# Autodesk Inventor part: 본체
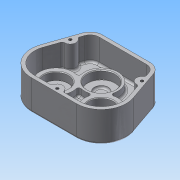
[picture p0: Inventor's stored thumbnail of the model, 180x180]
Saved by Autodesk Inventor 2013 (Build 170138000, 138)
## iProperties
Created: 2014-12
Part Number: 본체
Material: 알루미늄 6061
Document SubType Name: Modeling
Designer: Administrator
Mass: 614.49 g
Surface Area: 669.655 cm^2
Volume: 226.749 cm^3
Density: 2.71 g/cm^3
Author: Administrator
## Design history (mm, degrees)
sketch "스케치1"
  geometry: L1 (0, 32.527)-(-32.527, 0); L2 (0, 32.527)-(32.527, 0); L3 (47, 68.527)-(-47, 68.527); L4 (-66.565, 11.723)-(-47, 68.527); L5 (66.565, 11.723)-(47, 68.527); L6 (-32.527, -36)-(32.527, -36); A1 r 36 centre (-32.527, 0) between (-66.565, 11.723) and (-32.527, -36); A2 r 36 centre (32.527, 0) between (32.527, -36) and (66.565, 11.723); 1 further point
  constraints: 12 end point, 4 point on circle, 4 tangent, 2 centre point, 2 horizontal alignment, 1 equal length, 1 horizontal, 1 vertical alignment
  dimensions: "d0" = 72 diameter of A1; "d1" = 72 diameter of A2; "d3" = 90 deg angle of L1 L2; "d4" = 36 distance from line of L3 L1.start; "d5" = 94 distance of L3.start L3.end; "d25" = 46 distance of L1.start L1.end; "d26" = 46 distance of L1.start L2.end
extrude "돌출1" new body sketch "스케치1" distance "d6" = 44; taper "d7" = 0 deg
fillet "모깎기1" dims "d8" = 18
sketch "스케치2"
  geometry: L1 (-51.181, 56.389)-(-66.565, 11.723) reference; L2 (-32.527, -36)-(32.527, -36) reference; L3 (66.565, 11.723)-(51.181, 56.389) reference; L4 (34.162, 68.527)-(-34.162, 68.527) reference; L5 (-46.453, 54.76)-(-61.837, 10.095); L6 (-32.527, -31)-(32.527, -31); L7 (61.837, 10.095)-(46.453, 54.76); L8 (34.162, 63.527)-(-34.162, 63.527); A1 r 18 centre (-34.162, 50.527) between (-34.162, 68.527) and (-51.181, 56.389) reference; A2 r 36 centre (-32.527, 0) between (-66.565, 11.723) and (-32.527, -36) reference; A3 r 36 centre (32.527, 0) between (32.527, -36) and (66.565, 11.723) reference; A4 r 18 centre (34.162, 50.527) between (51.181, 56.389) and (34.162, 68.527) reference; A5 r 13 centre (-34.162, 50.527) between (-34.162, 63.527) and (-46.453, 54.76); A6 r 31 centre (-32.527, 0) between (-61.837, 10.095) and (-32.527, -31); A7 r 31 centre (32.527, 0) between (32.527, -31) and (61.837, 10.095); A8 r 13 centre (34.162, 50.527) between (46.453, 54.76) and (34.162, 63.527); 1 further point
  constraints: 8 end point, 8 point on circle, 4 centre point, 7 other
  dimensions: "d9" = 5 distance between parallel lines of L4 L8
extrude "돌출2" cut sketch "스케치2" distance "d11" = 34; taper "d12" = 0 deg
sketch "스케치3"
  geometry: L1 (-61.837, 10.095)-(-46.453, 54.76) reference; L2 (32.527, -31)-(-32.527, -31) reference; L3 (46.453, 54.76)-(61.837, 10.095) reference; L4 (-34.162, 68.527)-(34.162, 68.527) reference; A1 r 8 centre (-51.7, 39.527) between (-54.305, 31.963) and (-49.095, 47.091); A2 r 8 centre (51.7, 39.527) between (49.095, 47.091) and (54.305, 31.963); A3 r 8 centre (0, -31) between (8, -31) and (-8, -31); 1 further point
  constraints: 8 point on line, 6 point on circle, 3 centre point, 1 midpoint
  dimensions: "d13" = 16 diameter of A1; "d15" = 16 diameter of A2; "d16" = 29 distance from line of L4 A2.centre; "d17" = 29 distance from line of L4 A1.centre; "d18" = 16 diameter of A3
extrude "돌출3" join sketch "스케치3" distance "d19" = 34; taper "d20" = 0 deg
sketch "스케치4"
  geometry: C1 r 24 at (-32.527, 0); C2 r 24 at (32.527, 0); A1 r 31 centre (32.527, 0) between (32.527, -31) and (61.837, 10.095) reference; A2 r 31 centre (-32.527, 0) between (-61.837, 10.095) and (-32.527, -31) reference; 1 further point
  constraints: 2 centre point, 2 coincident
  dimensions: "d21" = 48 diameter of C1; "d22" = 48 diameter of C2
extrude "돌출4" join sketch "스케치4" distance "d23" = 11; taper "d24" = 0 deg
sketch "스케치5"
  geometry: C1 r 24 at (0, 0) reference; C2 r 24 at (-65.054, 0) reference; 1 further point
hole "구멍1" sketch "스케치5" at (-65.054, 0), (0, 0) diameter "d27" = 15.5; stored, may be unused: countersink angle "d31" = 90 deg, drill point angle "d33" = 0 deg; dims "d28" = 6, "d29" = 35, "d30" = 11, "d32" = 21
sketch "스케치6"
  geometry: C1 r 20 at (-32.527, 0); C2 r 20 at (32.527, 0); A1 r 36 centre (-32.527, 0) between (-66.565, 11.723) and (-32.527, -36) reference; A2 r 36 centre (32.527, 0) between (32.527, -36) and (66.565, 11.723) reference; 1 further point
  constraints: 2 centre point, 2 coincident
  dimensions: "d34" = 40 diameter of C1; "d35" = 40 diameter of C2
extrude "돌출5" join sketch "스케치6" distance "d36" = 7; taper "d37" = -10 deg
sketch "스케치7"
  geometry: C1 r 18.766 at (0, 0) reference; C2 r 18.766 at (65.054, 0) reference; 1 further point
hole "구멍2" sketch "스케치7" at (0, 0), (65.054, 0) diameter "d38" = 30; stored, may be unused: countersink angle "d42" = 90 deg, drill point angle "d44" = 0 deg; dims "d39" = 6, "d40" = 35, "d41" = 11, "d43" = 7
sketch "스케치8"
  geometry: L1 (-32.527, 0)-(0, 32.527); L2 (0, 32.527)-(32.527, 0); C1 r 24 at (0, 32.527); A1 r 31 centre (32.527, 0) between (32.527, -31) and (61.837, 10.095) reference; A2 r 31 centre (-32.527, 0) between (-61.837, 10.095) and (-32.527, -31) reference; 1 further point
  constraints: 4 end point, 1 centre point, 1 coincident, 1 perpendicular, 1 vertical alignment
  dimensions: "d45" = 46 distance of L1.end L2.end; "d46" = 48 diameter of C1
extrude "돌출6" join sketch "스케치8" distance "d47" = 11; taper "d48" = 0 deg
hole "구멍3" diameter "d51" = 20; stored, may be unused: countersink angle "d55" = 90 deg, drill point angle "d57" = 0 deg; dims "d49" = 10, "d50" = 10, "d52" = 6, "d53" = 40, "d54" = 12, "d56" = 15
fillet "모깎기2" dims "d58" = 0.3
fillet "모깎기3" dims "d59" = 0.1
chamfer "모따기1" distance "d60" = 1; stored, may be unused: second distance "d61" = 2, angle "d62" = 45 deg
fillet "모깎기4" dims "d63" = 3
fillet "모깎기5" dims "d64" = 3
fillet "모깎기6" dims "d65" = 3
fillet "모깎기7" dims "d66" = 3
sketch "스케치9"
  geometry: A1 r 8 centre (-51.7, 39.527) between (-52.144, 31.539) and (-47.131, 46.094) reference; A2 r 8 centre (51.7, 39.527) between (47.131, 46.094) and (52.144, 31.539) reference; A3 r 8 centre (0, -31) between (7.697, -28.818) and (-7.697, -28.818) reference; 4 further points
  constraints: 3 coincident
hole "구멍4" sketch "스케치9" at (-51.7, 39.527), (0, -31), (51.7, 39.527) diameter "d67" = 4.134; stored, may be unused: countersink angle "d71" = 90 deg, drill point angle "d73" = 118 deg; dims "d68" = 20, "d69" = 40, "d70" = 12, "d72" = 23
sketch "스케치10"
  geometry: L1 (34.162, 68.527)-(-34.162, 68.527); L2 (51.181, 56.389)-(66.565, 11.723) reference; L3 (32.527, -36)-(-32.527, -36) reference; L4 (-66.565, 11.723)-(-51.181, 56.389) reference; L5 (-34.162, 68.527)-(34.162, 68.527) reference; C1 r 14.9 at (32.527, 0) reference; C2 r 14.9 at (-32.527, 0) reference; C3 r 20 at (-32.527, 0) reference; C4 r 20 at (32.527, 0) reference; C5 r 7.75 at (32.527, 0) reference; C6 r 7.75 at (-32.527, 0) reference; A1 r 18 centre (34.162, 50.527) between (51.181, 56.389) and (34.162, 68.527) reference; A2 r 36 centre (32.527, 0) between (32.527, -36) and (66.565, 11.723) reference; A3 r 36 centre (-32.527, 0) between (-66.565, 11.723) and (-32.527, -36) reference; A4 r 18 centre (-34.162, 50.527) between (-34.162, 68.527) and (-51.181, 56.389) reference; 3 further points
  constraints: 2 end point, 1 coincident, 1 vertical alignment, 1 other
  dimensions: "d74" = 30 distance from line of L1 point (0, 38.527)
feature "엠보싱1" sketch "스케치10" dims "d0" = 72, "d1" = 72, "d3" = 90 deg, "d4" = 36, "d5" = 94, "d7" = 0, "d25" = 46, "d26" = 46, "d75" = 1, "d76" = 0
fillet "모깎기8" dims "d77" = 3
fillet "모깎기9" dims "d78" = 3
node "솔리드1"
node "투영된 루프1"
node "절단 모서리 투영1"
